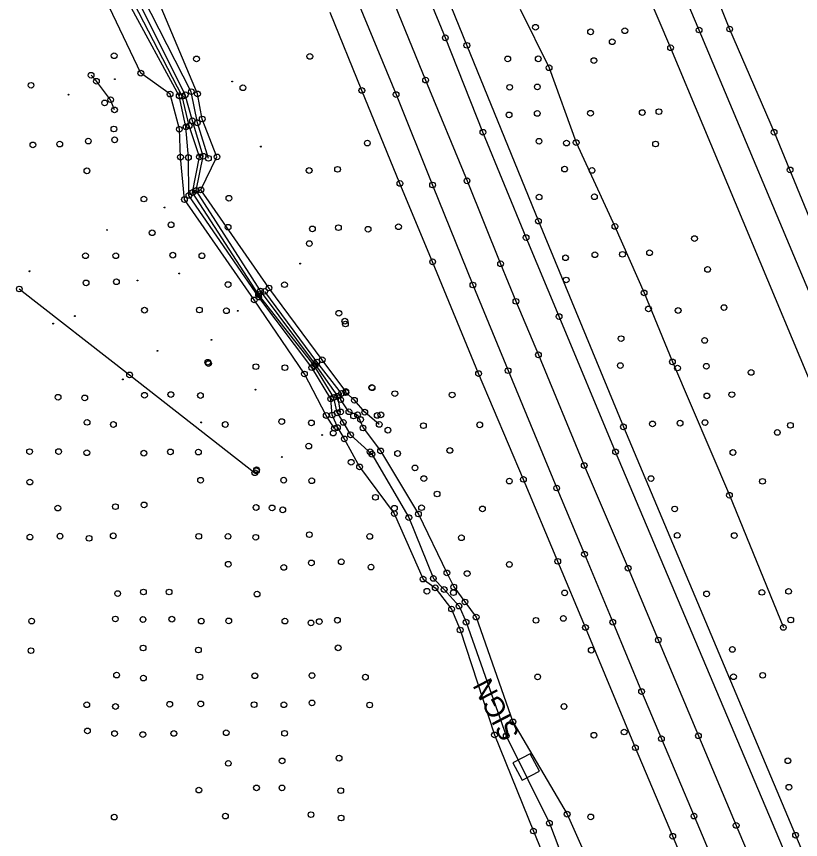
# Model space of a CAD drawing. Extents: x 20503438 to 20508873, y 7964251 to 7984667.
# Drawn here: x 20505737.9 to 20506012.3, y 7976120.1 to 7976408 of the extents above; entities that cross this region are included whole.
import ezdxf

# ---------------------------------------------------------------- set-up
doc = ezdxf.new("R2010")
doc.units = 0
for name, color, linetype in [('SurBreakLine', 7, 'Continuous'), ('SurControl', 7, 'Continuous'), ('SurDrainageArrowDown', 7, 'Continuous'), ('SurDrainageArrowUp', 7, 'Continuous'), ('SurEdgeRoadPaved', 7, 'Continuous'), ('SurEdgeShoulderPaved', 7, 'Continuous'), ('SurFenceWire', 7, 'Continuous'), ('SurPointsNonDTM', 7, 'Continuous'), ('SurRoadPoints', 7, 'Continuous'), ('SurSurveyPoints', 7, 'Continuous')]:
    doc.layers.add(name, color=color, linetype=linetype)

msp = doc.modelspace()

# ---------------------------------------------------------------- linework, layer by layer
at = {"layer": 'SurBreakLine'}
for points in [[(20505851.35, 7976269.67), (20505850.39, 7976275.15), (20505842.58, 7976286.3), (20505823.3, 7976311.97), (20505800.82, 7976347.13), (20505803.28, 7976359.11), (20505799.47, 7976371.49), (20505797.01, 7976380.62), (20505763.98, 7976446.94), (20505763.49, 7976460.26), (20505763.14, 7976462.66), (20505763.02, 7976473.12), (20505762.9, 7976474.96), (20505764.18, 7976478.87), (20505775.8, 7976474.23)], [(20505805.08, 7976358.37), (20505801.22, 7976370.79), (20505799.11, 7976381.69), (20505765.61, 7976447.27), (20505766.12, 7976460.43), (20505766.61, 7976461.98)], [(20505864.9, 7976265.29), (20505859.82, 7976269.57), (20505856.19, 7976273.73), (20505853.25, 7976276.46), (20505853.15, 7976276.84), (20505844.92, 7976287.91), (20505826.3, 7976313.02), (20505802.48, 7976347.34), (20505808.1, 7976358.88), (20505802.93, 7976372.13), (20505801.27, 7976380.91), (20505772.45, 7976449.51), (20505768.39, 7976459.59)], [(20505848.46, 7976268.58), (20505847.89, 7976274.23), (20505841.28, 7976285.15), (20505822.69, 7976309.83), (20505798.27, 7976345.4), (20505798.08, 7976358.65), (20505797.24, 7976369.41), (20505794.89, 7976380.24), (20505760.07, 7976444.31)], [(20505849.18, 7976263.92), (20505846.34, 7976268.41), (20505838.68, 7976282.94), (20505821.15, 7976308.83), (20505796.69, 7976343.96), (20505795.32, 7976358.82), (20505794.92, 7976368.53), (20505791.67, 7976380.85), (20505781.44, 7976388.17), (20505757.04, 7976439.33)], [(20505948.4, 7976440.27), (20505966.85, 7976397.06), (20506023.36, 7976261.75), (20506041.13, 7976219.76), (20506046.8, 7976206.26), (20506065.51, 7976161.54), (20506080.11, 7976126.62), (20506096.34, 7976088.07), (20506109.89, 7976056.1), (20506152.29, 7975956.2), (20506170.93, 7975911.54), (20506188.78, 7975869.57), (20506237.85, 7975752.64), (20506255.76, 7975710.06), (20506257.96, 7975704.85), (20506266.89, 7975683.65), (20506275.92, 7975662.23), (20506291.46, 7975625.08), (20506306.43, 7975588.4), (20506320.89, 7975553.64), (20506349.14, 7975482.98), (20506362.94, 7975447.73)], [(20505865.6, 7976423.82), (20505881.11, 7976385.76), (20505895.61, 7976350.5), (20505907.36, 7976321.51), (20505912.71, 7976308.35), (20505920.59, 7976289.64), (20505936.63, 7976250.91), (20505952.01, 7976214.99), (20505962.56, 7976189.88), (20505976.58, 7976156.36), (20505989.8, 7976125.02), (20505999.68, 7976101.54), (20506018.4, 7976056.86), (20506031.88, 7976024.8), (20506041.81, 7976001.38), (20506058.69, 7975961.74), (20506072.07, 7975930.1), (20506086.64, 7975895.86), (20506102.43, 7975858.26), (20506113.52, 7975831.94), (20506128.17, 7975796.98)], [(20505772.22, 7976375.33), (20505770.88, 7976378.89), (20505765.91, 7976385.35), (20505764.03, 7976387.44)], [(20505857.32, 7976268.64), (20505854.27, 7976269.74), (20505851.39, 7976273.94), (20505851.63, 7976276.12), (20505843.03, 7976287.13), (20505824.79, 7976311.84)], [(20505848.46, 7976268.58), (20505850.25, 7976264.2), (20505852.66, 7976260.22), (20505858.02, 7976250.41), (20505870.16, 7976234.1), (20505880.23, 7976211.18), (20505884.48, 7976208.12), (20505890.22, 7976200.71), (20505893.21, 7976193.38), (20505905.22, 7976156.68), (20505918.85, 7976123.05), (20505936.66, 7976079.7), (20505952.45, 7976040.57), (20505961.24, 7976024.82), (20505974.57, 7976000.9), (20505987.59, 7975979.73), (20505991.63, 7975968.17), (20505992.61, 7975964.84), (20505994.9, 7975959.75), (20505997.04, 7975945.54), (20506003.63, 7975923.63), (20506016.28, 7975882.58)], [(20505857.32, 7976268.64), (20505859.21, 7976264.04), (20505865.37, 7976256.03), (20505878.58, 7976233.95), (20505888.56, 7976213.34), (20505890.95, 7976208.42), (20505894.89, 7976203.18), (20505898.8, 7976197.89), (20505911.67, 7976161.23), (20505930.65, 7976128.95), (20505949.63, 7976086.15), (20505968.75, 7976044.23), (20505972.23, 7976028.9), (20505985.66, 7976003.51), (20505991.1, 7975980.4), (20505994.37, 7975970.45), (20505995.61, 7975967.2), (20505996.73, 7975960.88), (20505999.85, 7975946.76), (20506010.18, 7975927.08), (20506030.18, 7975888.29)]]:
    msp.add_lwpolyline(points, dxfattribs=at)
at = {"layer": 'SurControl'}
for centre in [(20505772.33, 7976386.07), (20505813.41, 7976385.23), (20505756.1, 7976380.64), (20505823.49, 7976362.48), (20505789.76, 7976341.19), (20505769.61, 7976333.3), (20505837.22, 7976321.54), (20505742.51, 7976318.87), (20505794.89, 7976318.11), (20505780.29, 7976315.63), (20505815.35, 7976305.05), (20505758.37, 7976303.19), (20505750.75, 7976300.55), (20505806.13, 7976294.89), (20505787.23, 7976291.01), (20505775.12, 7976281.03), (20505821.59, 7976277.44), (20505802.6, 7976266.01), (20505844.92, 7976261.58), (20505830.76, 7976253.9)]:
    msp.add_circle(centre, 0.15, dxfattribs=at)
at = {"layer": 'SurDrainageArrowDown'}
msp.add_lwpolyline([(20505850.17, 7976269.3), (20505848.97, 7976274.71), (20505842.08, 7976285.87), (20505822.66, 7976310.74), (20505799.52, 7976346.43), (20505801.98, 7976358.86), (20505798.41, 7976369.76), (20505795.88, 7976380.07), (20505762.28, 7976445.12), (20505763.13, 7976460.19), (20505762.72, 7976462.82), (20505761.71, 7976473.28), (20505762.28, 7976476.74), (20505762.78, 7976478.85)], dxfattribs=at)
at = {"layer": 'SurDrainageArrowUp'}
for points in [[(20505914.25, 7976410.54), (20505924.33, 7976390.07), (20505933.81, 7976363.88), (20505947.37, 7976334.57), (20505957.59, 7976311.31), (20505967.5, 7976287.17), (20505987.45, 7976240.5), (20506006.32, 7976194.28)], [(20505850.17, 7976269.3), (20505852.31, 7976266), (20505854.86, 7976261.64), (20505862.3, 7976254.88), (20505875.24, 7976232.69), (20505883.82, 7976211.4), (20505887.61, 7976207.55), (20505892.81, 7976201.72), (20505895.29, 7976196.12), (20505909.35, 7976156.32), (20505924.45, 7976125.82), (20505940.83, 7976082.68), (20505959.76, 7976045.64), (20505968.59, 7976027.18), (20505979.13, 7976002.88), (20505989.48, 7975979.63), (20505992.64, 7975969.29), (20505993.74, 7975966.75), (20505995.68, 7975960.63), (20505998.59, 7975946.26), (20506005.17, 7975924.32), (20506024.41, 7975886.68)]]:
    msp.add_lwpolyline(points, dxfattribs=at)
at = {"layer": 'SurEdgeRoadPaved'}
for points in [[(20505973.34, 7976438.98), (20505987.53, 7976403.61), (20506003.07, 7976367.49), (20506018.95, 7976328.88), (20506025.44, 7976313.31), (20506044.67, 7976267.48), (20506061.06, 7976228.29), (20506067.76, 7976212.43), (20506081.36, 7976180.25), (20506103.2, 7976128.63), (20506112.1, 7976107.56), (20506128.65, 7976068.25), (20506136.4, 7976049.83), (20506153.65, 7976009.14), (20506168.49, 7975974.01), (20506178.44, 7975950.63), (20506193.04, 7975916.4), (20506208.43, 7975879.89), (20506224.55, 7975842.62), (20506237.48, 7975811.98)], [(20506278.91, 7975465.84), (20506257.71, 7975518.12), (20506250.34, 7975536.21), (20506236.76, 7975569.18), (20506175.22, 7975717.06), (20506144.4, 7975789.63), (20506112.25, 7975866.01), (20506069.58, 7975966.38), (20506037.98, 7976041.41), (20506015.97, 7976094.11), (20505947.59, 7976255.69), (20505927.83, 7976303), (20505916.28, 7976330.64), (20505901.17, 7976367.49), (20505888.02, 7976400.52), (20505875.61, 7976430.87)], [(20505854.48, 7976420.23), (20505870.79, 7976380.67), (20505883.55, 7976349.04), (20505897.65, 7976314.07), (20505909.99, 7976284.1), (20505926.99, 7976243.04), (20505936.73, 7976219.88), (20505946.63, 7976196.12), (20505956.71, 7976171.82), (20505963.64, 7976155.35), (20505975.06, 7976128.28), (20505995.52, 7976079.78), (20506006.7, 7976053.21), (20506016.58, 7976029.7), (20506033.67, 7975989.39), (20506044.1, 7975964.93), (20506057.48, 7975933.32), (20506076.87, 7975887.68), (20506087.41, 7975862.83), (20506092.07, 7975851.84), (20506114.77, 7975798.09)], [(20506375.71, 7975448.39), (20506362.64, 7975481.5), (20506329.83, 7975562.96), (20506317.59, 7975593.18), (20506238.7, 7975783.34), (20506212.9, 7975845.26), (20506167.37, 7975951.08), (20506129.46, 7976040.57), (20506122.49, 7976056.94), (20506110.39, 7976085.68), (20506105.99, 7976096.14), (20506091.81, 7976130.11), (20506074.2, 7976171.54), (20506054.82, 7976217.77), (20506019.21, 7976302.51), (20505976.84, 7976403.26), (20505970.11, 7976419.35)], [(20506093.39, 7975823.17), (20506078.53, 7975858.38), (20506066.58, 7975886.62), (20506057.75, 7975907.79), (20506045.94, 7975935.43), (20506040.16, 7975949.09), (20506027.46, 7975979.19), (20506009.5, 7976021.69), (20505992.28, 7976062.56), (20505979.1, 7976093.75), (20505967.62, 7976121.21), (20505954.55, 7976152.2), (20505937.07, 7976194.25), (20505927.35, 7976217.39), (20505915.34, 7976246.07), (20505899.65, 7976283.07), (20505883.58, 7976322.17), (20505872.12, 7976349.6), (20505858.8, 7976382.12), (20505847.76, 7976409.43)]]:
    msp.add_lwpolyline(points, dxfattribs=at)
at = {"layer": 'SurEdgeShoulderPaved'}
msp.add_lwpolyline([(20505889.98, 7976411.65), (20505895.55, 7976397.9), (20505920.61, 7976336.44), (20505950.34, 7976264.44), (20506010.6, 7976121.59), (20506025.61, 7976085.79), (20506040.8, 7976049.02), (20506074.56, 7975969.59), (20506097.02, 7975916.55), (20506142.06, 7975809.67), (20506177.13, 7975727.28), (20506237.29, 7975584.09), (20506267.06, 7975511.74), (20506296.53, 7975437.96)], dxfattribs=at)
at = {"layer": 'SurFenceWire'}
msp.add_lwpolyline([(20505738.91, 7976312.67), (20505777.5, 7976282.6), (20505821.33, 7976248.37)], dxfattribs=at)
at = {"layer": 'SurPointsNonDTM'}
for centre in [(20505817.17, 7976383.07), (20505768.78, 7976377.76), (20505772.03, 7976368.63), (20505785.41, 7976332.33), (20505840.41, 7976328.54), (20505738.91, 7976312.67), (20505852.84, 7976301.41), (20505853.06, 7976300.42), (20505804.88, 7976287.05), (20505805.13, 7976286.58), (20505777.5, 7976282.6), (20505862.29, 7976278.25), (20505862.39, 7976278.11), (20505855.91, 7976268.24), (20505864.19, 7976268.42), (20505865.45, 7976268.64), (20505848.77, 7976262.25), (20505840.2, 7976257.72), (20505821.97, 7976249.41), (20505821.33, 7976248.37), (20505821.89, 7976249.09), (20505827.38, 7976236.08), (20505843.89, 7976196.32)]:
    msp.add_circle(centre, 1, dxfattribs=at)
at = {"layer": 'SurRoadPoints'}
msp.add_lwpolyline([(20505919.33, 7976147.04), (20505919.33, 7976147.04), (20505917.74, 7976150.07), (20505911.68, 7976146.9), (20505914.86, 7976140.83), (20505920.92, 7976144.01), (20505919.34, 7976147.04)], dxfattribs=at)
at = {"layer": 'SurSurveyPoints'}
for centre in [(20505919.57, 7976404.24), (20505938.87, 7976402.62), (20505950.84, 7976403.02), (20505976.84, 7976403.26), (20505987.53, 7976403.61), (20505888.02, 7976400.52), (20505946.42, 7976399.15), (20505895.55, 7976397.9), (20505966.85, 7976397.06), (20505772.11, 7976394.26), (20505840.59, 7976394.02), (20505800.93, 7976393.15), (20505909.87, 7976393.16), (20505920.55, 7976393.18), (20505940, 7976392.58), (20505781.44, 7976388.17), (20505924.33, 7976390.07), (20505764.03, 7976387.44), (20505765.91, 7976385.35), (20505881.11, 7976385.76), (20505743.01, 7976383.92), (20505858.8, 7976382.12), (20505910.54, 7976383.22), (20505920.22, 7976383.35), (20505770.88, 7976378.89), (20505791.67, 7976380.85), (20505794.89, 7976380.24), (20505795.88, 7976380.07), (20505797.01, 7976380.62), (20505799.11, 7976381.69), (20505801.27, 7976380.91), (20505870.79, 7976380.67), (20505772.22, 7976375.33), (20505910.33, 7976373.58), (20505920.18, 7976374.09), (20505938.82, 7976374.13), (20505956.94, 7976374.39), (20505962.77, 7976374.7), (20505799.47, 7976371.49), (20505801.22, 7976370.79), (20505802.93, 7976372.13), (20505794.92, 7976368.53), (20505797.24, 7976369.41), (20505798.41, 7976369.76), (20505901.17, 7976367.49), (20506003.07, 7976367.49), (20505772.28, 7976364.84), (20505743.66, 7976363.06), (20505753.05, 7976363.36), (20505763.06, 7976364.41), (20505860.72, 7976363.72), (20505920.8, 7976364.34), (20505930.42, 7976363.72), (20505933.81, 7976363.88), (20505961.61, 7976363.39), (20505795.32, 7976358.82), (20505801.98, 7976358.86), (20505803.28, 7976359.11), (20505808.1, 7976358.88), (20505798.08, 7976358.65), (20505805.08, 7976358.37), (20505762.58, 7976354.01), (20505840.36, 7976354.11), (20505850.3, 7976354.52), (20505929.76, 7976354.6), (20505939.36, 7976354.16), (20506008.68, 7976354.32), (20505895.61, 7976350.5), (20505802.48, 7976347.34), (20505872.12, 7976349.6), (20505883.55, 7976349.04), (20505798.27, 7976345.4), (20505799.52, 7976346.43), (20505800.82, 7976347.13), (20505812.27, 7976344.41), (20505920.84, 7976344.84), (20505940.19, 7976344.94), (20505782.51, 7976344.14), (20505796.69, 7976343.96), (20505920.61, 7976336.44), (20505792.02, 7976335.13), (20505811.97, 7976334.25), (20505841.5, 7976333.7), (20505850.58, 7976334.12), (20505860.98, 7976333.56), (20505871.62, 7976334.45), (20505947.37, 7976334.57), (20505916.28, 7976330.64), (20505975.23, 7976330.3), (20505762.07, 7976324.29), (20505772.68, 7976324.3), (20505792.63, 7976324.5), (20505802.83, 7976324.28), (20505940.35, 7976324.66), (20505950.03, 7976324.79), (20505959.49, 7976325.34), (20505883.58, 7976322.17), (20505907.36, 7976321.51), (20505930.09, 7976323.58), (20505979.81, 7976319.53), (20505930.32, 7976315.82), (20505762.28, 7976314.81), (20505772.9, 7976315.18), (20505811.98, 7976314.21), (20505826.3, 7976313.02), (20505831.73, 7976314.17), (20505897.65, 7976314.07), (20505822.66, 7976310.74), (20505822.69, 7976309.83), (20505823.3, 7976311.97), (20505824.79, 7976311.84), (20505957.59, 7976311.31), (20505821.15, 7976308.83), (20505912.71, 7976308.35), (20505782.73, 7976305.26), (20505801.95, 7976305.32), (20505811.39, 7976305.06), (20505850.74, 7976304.18), (20505959.13, 7976305.69), (20505969.51, 7976305.14), (20505985.54, 7976306.18), (20505927.83, 7976303), (20505949.52, 7976295.3), (20505978.78, 7976294.69), (20505920.59, 7976289.64), (20505843.03, 7976287.13), (20505844.92, 7976287.91), (20505967.5, 7976287.17), (20505821.71, 7976285.5), (20505831.87, 7976285.14), (20505841.28, 7976285.15), (20505842.08, 7976285.87), (20505842.58, 7976286.3), (20505909.99, 7976284.1), (20505949.26, 7976285.87), (20505969.28, 7976285.02), (20505979.37, 7976285.65), (20505838.68, 7976282.94), (20505899.65, 7976283.07), (20505995.04, 7976283.48), (20505995.04, 7976283.48), (20505782.72, 7976275.5), (20505791.95, 7976275.74), (20505802.31, 7976275.41), (20505851.63, 7976276.12), (20505853.15, 7976276.84), (20505853.25, 7976276.46), (20505870.34, 7976276.06), (20505890.41, 7976275.59), (20505979.55, 7976275.28), (20505988.29, 7976275.71), (20505752.49, 7976274.8), (20505761.82, 7976274.55), (20505847.89, 7976274.23), (20505848.97, 7976274.71), (20505850.39, 7976275.15), (20505851.39, 7976273.94), (20505856.19, 7976273.73), (20505851.35, 7976269.67), (20505854.27, 7976269.74), (20505859.82, 7976269.57), (20505846.34, 7976268.41), (20505848.46, 7976268.58), (20505850.17, 7976269.3), (20505857.32, 7976268.64), (20505858.35, 7976266.99), (20505762.63, 7976266.01), (20505771.83, 7976265.26), (20505811, 7976265.27), (20505830.76, 7976266.28), (20505841.13, 7976265.83), (20505849.18, 7976263.92), (20505850.25, 7976264.2), (20505852.31, 7976266), (20505859.21, 7976264.04), (20505864.9, 7976265.29), (20505880.34, 7976264.86), (20505900.06, 7976265.15), (20505950.34, 7976264.44), (20505960.53, 7976265.46), (20505970.17, 7976265.73), (20505978.9, 7976265.93), (20506008.78, 7976264.97), (20505854.86, 7976261.64), (20505867.92, 7976263.28), (20506004.21, 7976262.48), (20505852.66, 7976260.22), (20505742.52, 7976255.77), (20505752.67, 7976255.78), (20505762.55, 7976255.39), (20505782.5, 7976255.23), (20505791.79, 7976255.69), (20505801.58, 7976255.62), (20505861.71, 7976255.72), (20505865.37, 7976256.03), (20505871.32, 7976255.11), (20505889.59, 7976256.18), (20505947.59, 7976255.69), (20505988.66, 7976255.46), (20505862.3, 7976254.88), (20505855.06, 7976252.04), (20505858.02, 7976250.41), (20505877.4, 7976250.07), (20505936.63, 7976250.91), (20505742.59, 7976245.13), (20505802.37, 7976245.77), (20505831.44, 7976245.79), (20505841.27, 7976245.59), (20505880.49, 7976246.35), (20505910.42, 7976245.46), (20505915.34, 7976246.07), (20505960.01, 7976246.35), (20505999.03, 7976245.38), (20505885.15, 7976240.95), (20505926.99, 7976243.04), (20505863.55, 7976239.79), (20505987.45, 7976240.5), (20505752.39, 7976236.02), (20505772.54, 7976236.52), (20505782.59, 7976237.13), (20505821.78, 7976236.23), (20505831.12, 7976235.41), (20505870.18, 7976235.97), (20505879.69, 7976236.16), (20505901.01, 7976235.72), (20505968.29, 7976235.71), (20505870.16, 7976234.1), (20505875.24, 7976232.69), (20505878.58, 7976233.95), (20505771.8, 7976226.31), (20505840.42, 7976226.72), (20505969.18, 7976226.48), (20505989.14, 7976226.4), (20505742.62, 7976225.89), (20505753.15, 7976226.19), (20505763.32, 7976225.44), (20505801.7, 7976226.14), (20505811.96, 7976226.13), (20505821.65, 7976225.8), (20505861.55, 7976226.12), (20505893.64, 7976225.65), (20505936.73, 7976219.88), (20505812.05, 7976216.38), (20505831.48, 7976215.27), (20505841.14, 7976216.84), (20505851.59, 7976217.25), (20505862.01, 7976215.4), (20505910.41, 7976216.32), (20505927.35, 7976217.39), (20505952.01, 7976214.99), (20505888.56, 7976213.34), (20505895.65, 7976213.1), (20505880.23, 7976211.18), (20505883.82, 7976211.4), (20505782.36, 7976206.66), (20505791.35, 7976206.67), (20505881.58, 7976206.93), (20505884.48, 7976208.12), (20505887.61, 7976207.55), (20505890.84, 7976206.44), (20505890.95, 7976208.42), (20505929.79, 7976206.33), (20505998.8, 7976206.54), (20506008.15, 7976206.89), (20505773.34, 7976206.11), (20505822.13, 7976205.95), (20505979.46, 7976206), (20505890.22, 7976200.71), (20505892.81, 7976201.72), (20505894.89, 7976203.18), (20505898.8, 7976197.89), (20505743.23, 7976196.5), (20505772.52, 7976197.23), (20505782.2, 7976197.04), (20505792.29, 7976197.16), (20505802.59, 7976196.48), (20505812.22, 7976196.56), (20505831.88, 7976196.49), (20505841, 7976195.86), (20505850.25, 7976196.8), (20505895.29, 7976196.12), (20505919.74, 7976196.75), (20505929.32, 7976197.44), (20505946.63, 7976196.12), (20506008.91, 7976196.87), (20505893.21, 7976193.38), (20505937.07, 7976194.25), (20506006.32, 7976194.28), (20505962.56, 7976189.88), (20505743, 7976186.14), (20505782.24, 7976187.08), (20505801.6, 7976186.38), (20505850.51, 7976187.14), (20505939.08, 7976186.31), (20505988.47, 7976186.57), (20505772.96, 7976177.6), (20505821.34, 7976177.35), (20505841.35, 7976177.43), (20505999.09, 7976177.52), (20505782.35, 7976176.57), (20505802.11, 7976176.93), (20505860.04, 7976176.88), (20505920.33, 7976176.97), (20505988.87, 7976177.03), (20505956.71, 7976171.82), (20505762.53, 7976167.23), (20505772.57, 7976166.61), (20505791.55, 7976167.4), (20505802.42, 7976167.5), (20505821.09, 7976167.25), (20505831.51, 7976167.23), (20505841.35, 7976167.87), (20505861.53, 7976167.13), (20505929.55, 7976166.61), (20505911.67, 7976161.23), (20505762.76, 7976158.08), (20505811.32, 7976157.43), (20505831.77, 7976157.23), (20505950.6, 7976157.68), (20505772.24, 7976157.13), (20505782.14, 7976156.79), (20505792.99, 7976157.18), (20505905.22, 7976156.68), (20505909.35, 7976156.32), (20505940.02, 7976156.57), (20505963.64, 7976155.35), (20505976.58, 7976156.36), (20505954.55, 7976152.2), (20505812.06, 7976146.72), (20505830.9, 7976147.58), (20505850.82, 7976148.53), (20506007.9, 7976147.62), (20505801.76, 7976137.37), (20505821.92, 7976138.15), (20505830.85, 7976138.15), (20505851.42, 7976137.17), (20506008.28, 7976138.35), (20505841, 7976128.77), (20505930.65, 7976128.95), (20505772.14, 7976127.91), (20505811.03, 7976128.26), (20505851.53, 7976127.61), (20505924.45, 7976125.82), (20505938.92, 7976127.97), (20505975.06, 7976128.28), (20505918.85, 7976123.05), (20505989.8, 7976125.02), (20505967.62, 7976121.21), (20506010.6, 7976121.59)]:
    msp.add_circle(centre, 1, dxfattribs=at)

# ---------------------------------------------------------------- texts
at = {"layer": 'SurRoadPoints'}
msp.add_text('SIGN', height=6.995, rotation=117.654, dxfattribs=at).set_placement((20505914.2, 7976157))

doc.saveas('drawing.dxf')
